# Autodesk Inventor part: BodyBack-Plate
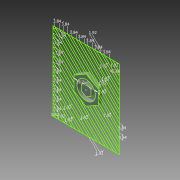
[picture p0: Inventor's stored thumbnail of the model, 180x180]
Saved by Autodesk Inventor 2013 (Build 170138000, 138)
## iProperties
Created: 2013-04
Part Number: BodyBack-Plate
Material: Generic
Document SubType Name: Modeling
Designer: frankenteddy
Density: 1 g/cm^3
Author: frankenteddy
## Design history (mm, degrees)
sketch "Sketch1"
  geometry: L1 (26.4, -9.301)-(26.4, -13.141); L2 (-3.935, 2.272)-(0, 4.543); L3 (-21.033, 31.2)-(-26.4, 31.2); L4 (-26.4, 25.833)-(-21.033, 31.2); L5 (-26.4, 23.117)-(-18.317, 31.2); L6 (-26.4, 23.117)-(-14.97, 23.117); L7 (-26.4, 19.277)-(-26.4, 23.117); L8 (-18.317, 31.2)-(-14.477, 31.2); L9 (-14.477, 31.2)-(-26.4, 19.277); L10 (-11.762, 31.2)-(-7.922, 31.2); L11 (-26.4, 16.562)-(-11.762, 31.2); L12 (-7.922, 31.2)-(-26.4, 12.722); L13 (-26.4, 10.007)-(-5.207, 31.2); L14 (-1.367, 31.2)-(-26.4, 6.167); L15 (-9.6, 5.543)-(0, 11.085); L16 (-26.4, 3.452)-(1.348, 31.2); L17 (-9.6, -5.543)-(-9.6, 5.543); L18 (5.188, 31.2)-(-26.4, -0.388); L19 (-26.4, -3.104)-(7.904, 31.2); L20 (-26.4, -9.659)-(14.459, 31.2); L21 (11.744, 31.2)-(-26.4, -6.944); L22 (-26.4, -0.388)-(-26.4, 3.452); L23 (9.6, -5.543)-(0, -11.085); L24 (-26.4, 16.562)-(-26.4, 12.722); L25 (-26.4, 10.007)-(-26.4, 6.167); L26 (-5.207, 31.2)-(-1.367, 31.2); L27 (-26.4, 31.2)-(-26.4, 25.833); L28 (14.459, 31.2)-(18.299, 31.2); L29 (26.4, 30.03)-(26.4, 26.19); L30 (21.014, 31.2)-(24.854, 31.2); L31 (7.904, 31.2)-(11.744, 31.2); L32 (26.4, 23.475)-(26.4, 19.635); L33 (1.348, 31.2)-(5.188, 31.2); L34 (26.4, 16.92)-(26.4, 13.08); L35 (18.299, 31.2)-(-4.296, 8.605); L36 (0.57, 10.756)-(21.014, 31.2); L37 (26.4, 10.365)-(26.4, 6.525); L38 (26.4, 19.635)-(9.6, 2.835); L39 (26.4, 3.809)-(26.4, -0.031); L40 (9.6, 0.12)-(26.4, 16.92); L41 (26.4, 13.08)-(9.6, -3.72); L42 (8.882, 5.957)-(26.4, 23.475); L43 (26.4, 26.19)-(7.161, 6.951); L44 (4.726, 8.357)-(26.4, 30.03); L45 (24.854, 31.2)-(3.005, 9.35); L46 (9.6, 5.543)-(9.6, -5.543); L47 (0, 11.085)-(9.6, 5.543); L48 (26.4, -2.746)-(26.4, -6.586); L49 (26.4, -15.857)-(26.4, -19.697); L50 (11.057, -31.2)-(26.4, -15.857); L51 (26.4, -13.141)-(8.341, -31.2); L52 (8.341, -31.2)-(4.501, -31.2); L53 (4.501, -31.2)-(26.4, -9.301); L54 (0, 4.543)-(3.935, 2.272); L55 (26.4, -6.586)-(1.786, -31.2); L56 (-2.054, -31.2)-(26.4, -2.746); L57 (26.4, -0.031)-(-4.769, -31.2); L58 (-8.609, -31.2)-(26.4, 3.809); L59 (-15.165, -31.2)-(26.4, 10.365); L60 (26.4, 6.525)-(-11.325, -31.2); L61 (26.4, -19.697)-(14.897, -31.2); L62 (14.897, -31.2)-(11.057, -31.2); L63 (17.612, -31.2)-(26.4, -22.412); L64 (21.452, -31.2)-(17.612, -31.2)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; C1 r 7.367 at (0, 0); 5 further points
  constraints: 186 end point, 59 parallel, 18 point on line, 17 perpendicular, 2 coincident, 1 centre point, 1 equal length, 1 horizontal, 1 vertical, 106 other
  dimensions: "d0" = 19.2 distance between parallel lines of L46 L17; "d1" = 45 deg angle of L6 L5; "d2" = 3.84 distance of L5.end L8.end; "d3" = 3.84 distance of L10.start L10.end; "d4" = 1.92 distance between parallel lines of L11 L9; "d5" = 3.84 distance of L13.end L14.start; "d6" = 1.92 distance between parallel lines of L13 L12; "d7" = 3.84 distance of L16.end L18.start; "d8" = 1.92 distance between parallel lines of L16 L14; "d9" = 3.84 distance of L19.end L21.start; "d10" = 1.92 distance between parallel lines of L19 L18; "d11" = 3.84 distance of L20.end L28.end; "d12" = 1.92 distance between parallel lines of L20 L21; "d13" = 3.84 distance of L30.start L30.end; "d14" = 3.84 distance of L29.start L29.end; "d15" = 3.84 distance of L84.end L80.start; "d16" = 1.92 distance between parallel lines of L79 L80; "d17" = 3.84 distance of L79.end L20.start; "d18" = 3.84 distance of L32.start L32.end; "d19" = 3.84 distance of L34.start L34.end; "d20" = 3.84 distance of L37.start L37.end; "d21" = 3.84 distance of L39.start L39.end; "d22" = 1.92 distance between parallel lines of L58 L60; "d23" = 3.84 distance of L48.start L48.end; "d24" = 1.92 distance between parallel lines of L56 L57; "d25" = 3.84 distance of L1.start L1.end; "d26" = 1.92 distance between parallel lines of L53 L55; "d27" = 3.84 distance of L49.start L49.end; "d28" = 1.92 distance between parallel lines of L50 L51; "d29" = 3.84 distance of L63.end L65.start; "d30" = 1.92 distance between parallel lines of L63 L61; "d31" = 1.92 distance between parallel lines of L67 L65; "d32" = 1.92 distance between parallel lines of L5 L4
extrude "Extrusion3" new body sketch "Sketch1" distance "d42" = 3; taper "d43" = 0 deg
body "Solid2"
